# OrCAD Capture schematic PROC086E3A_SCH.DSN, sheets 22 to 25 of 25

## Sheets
22 11. AUDIO I/F - CODEC - B: size C; title: AUDIO I/F CODEC - B
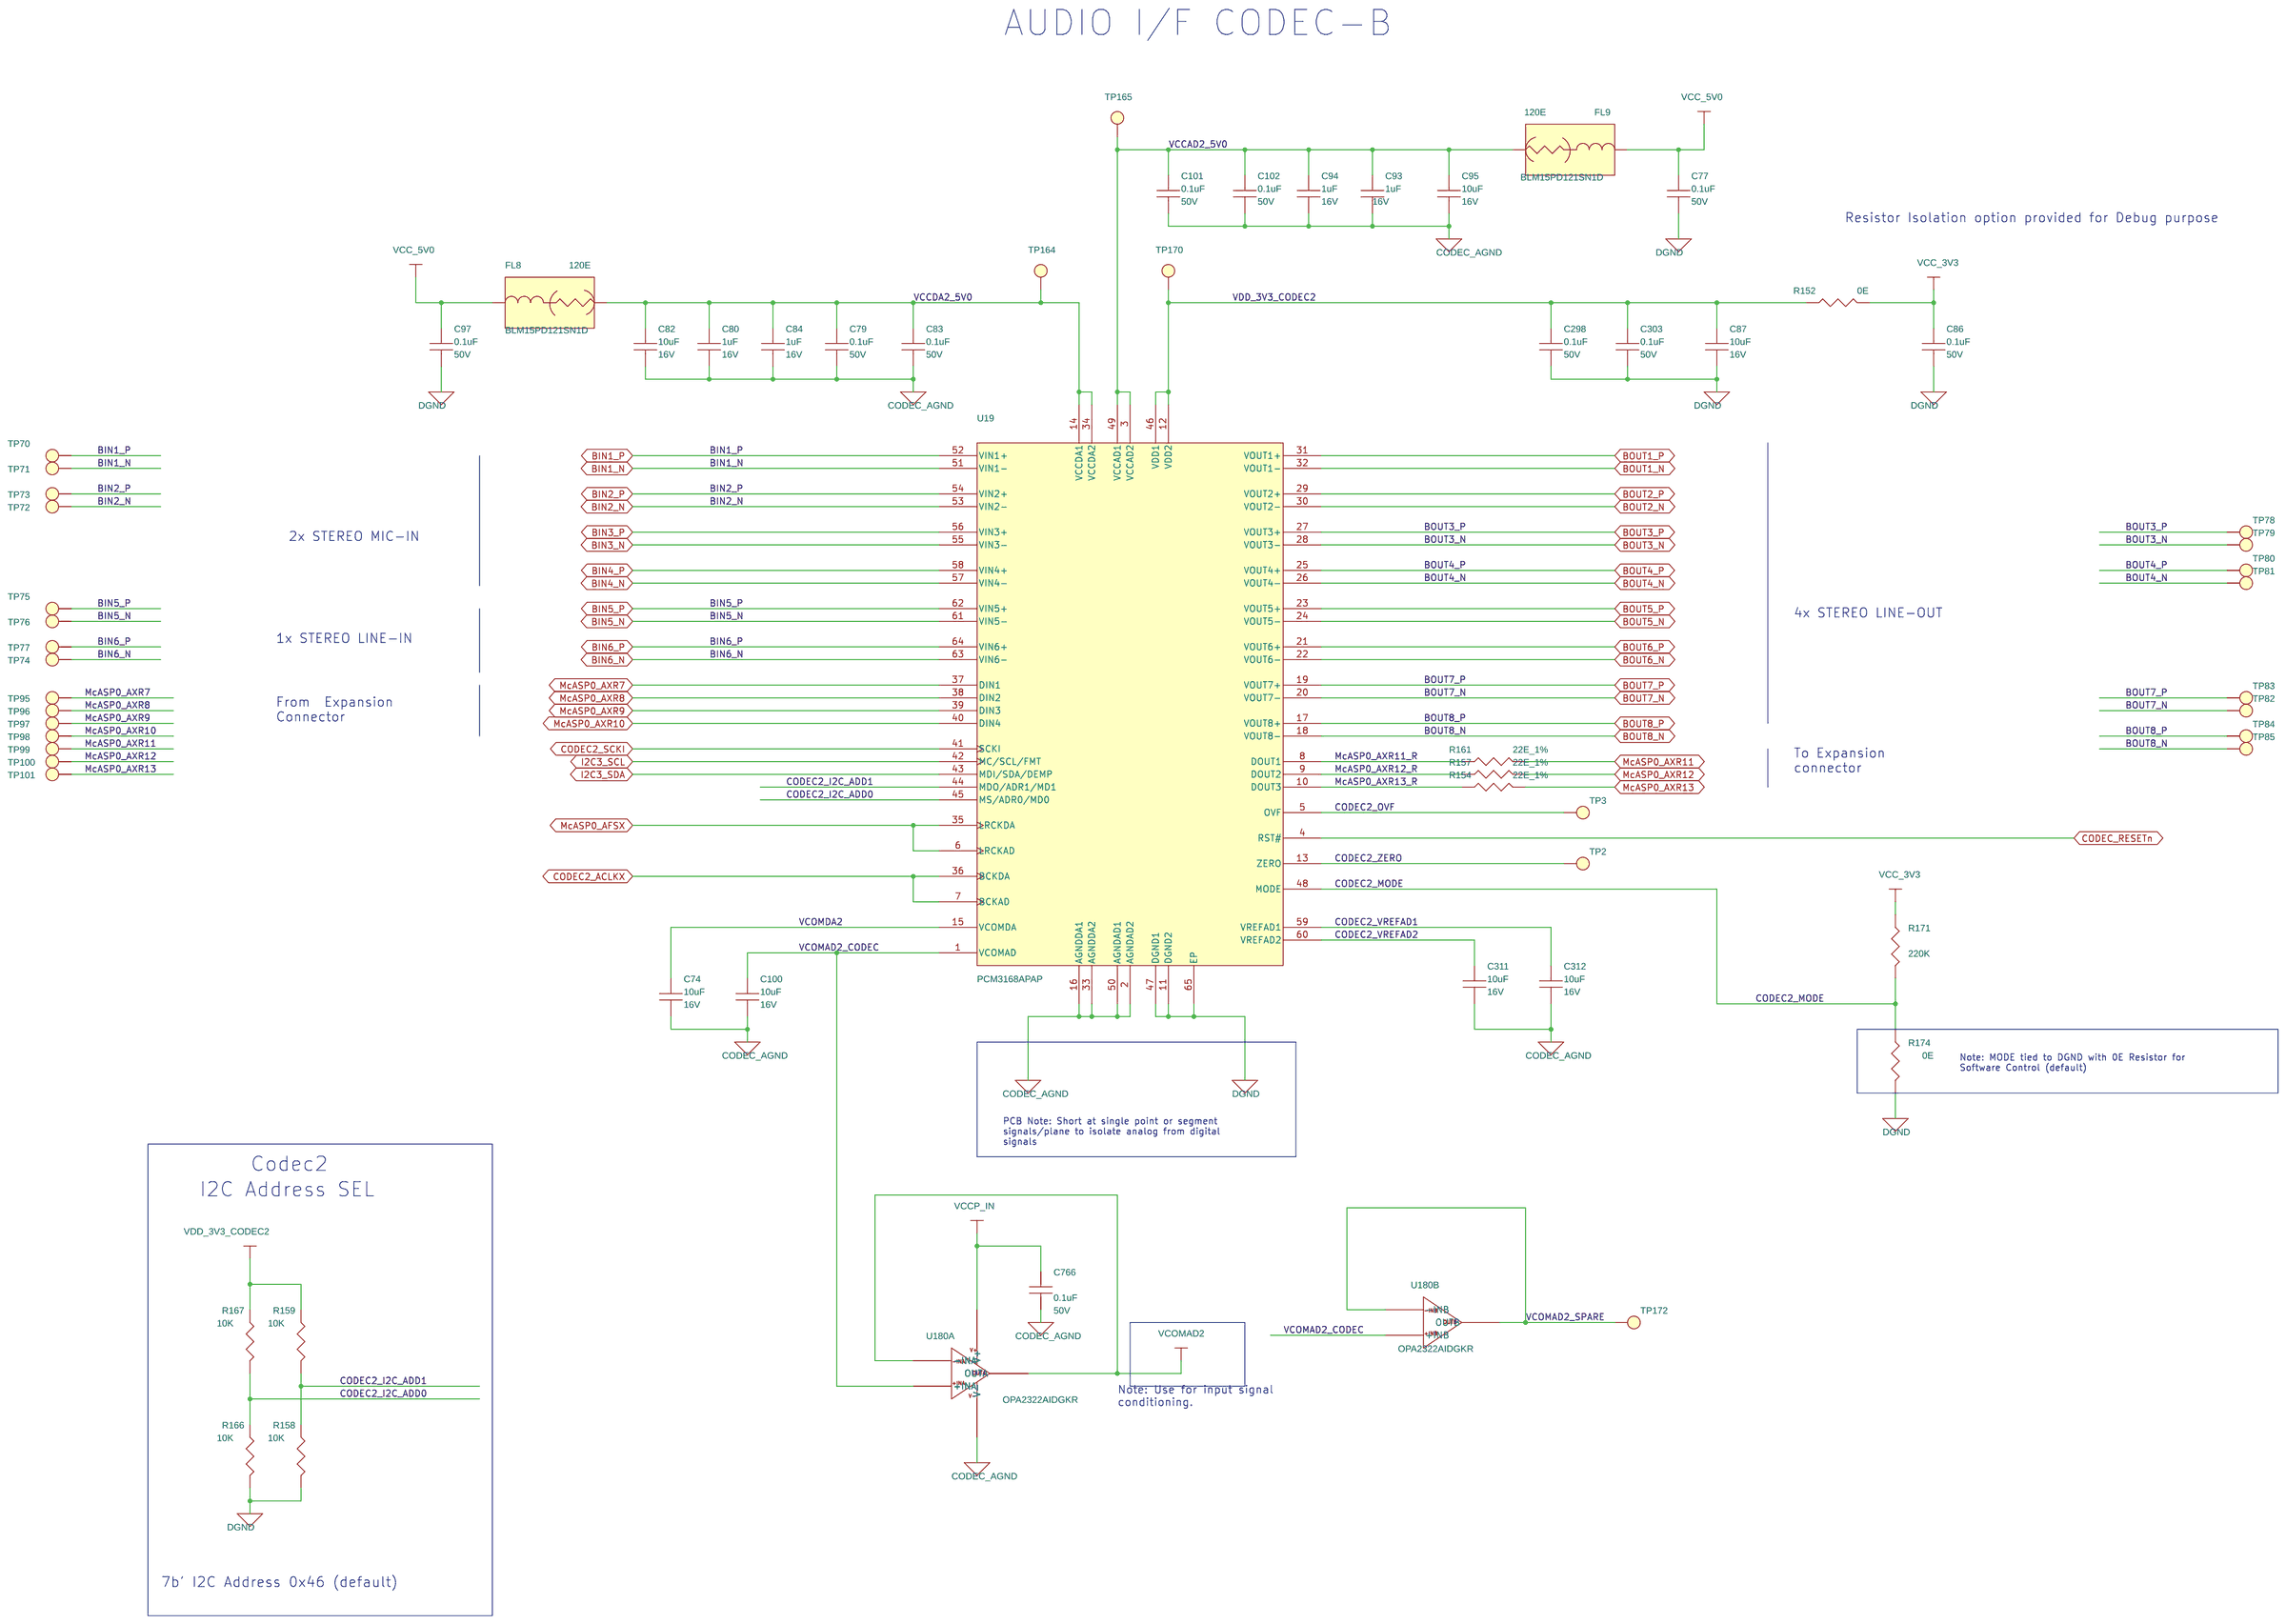
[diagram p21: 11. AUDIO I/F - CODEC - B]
23 06. AUDIO I/F - CODEC - A: size C; title: AUDIO I/F CODEC - A
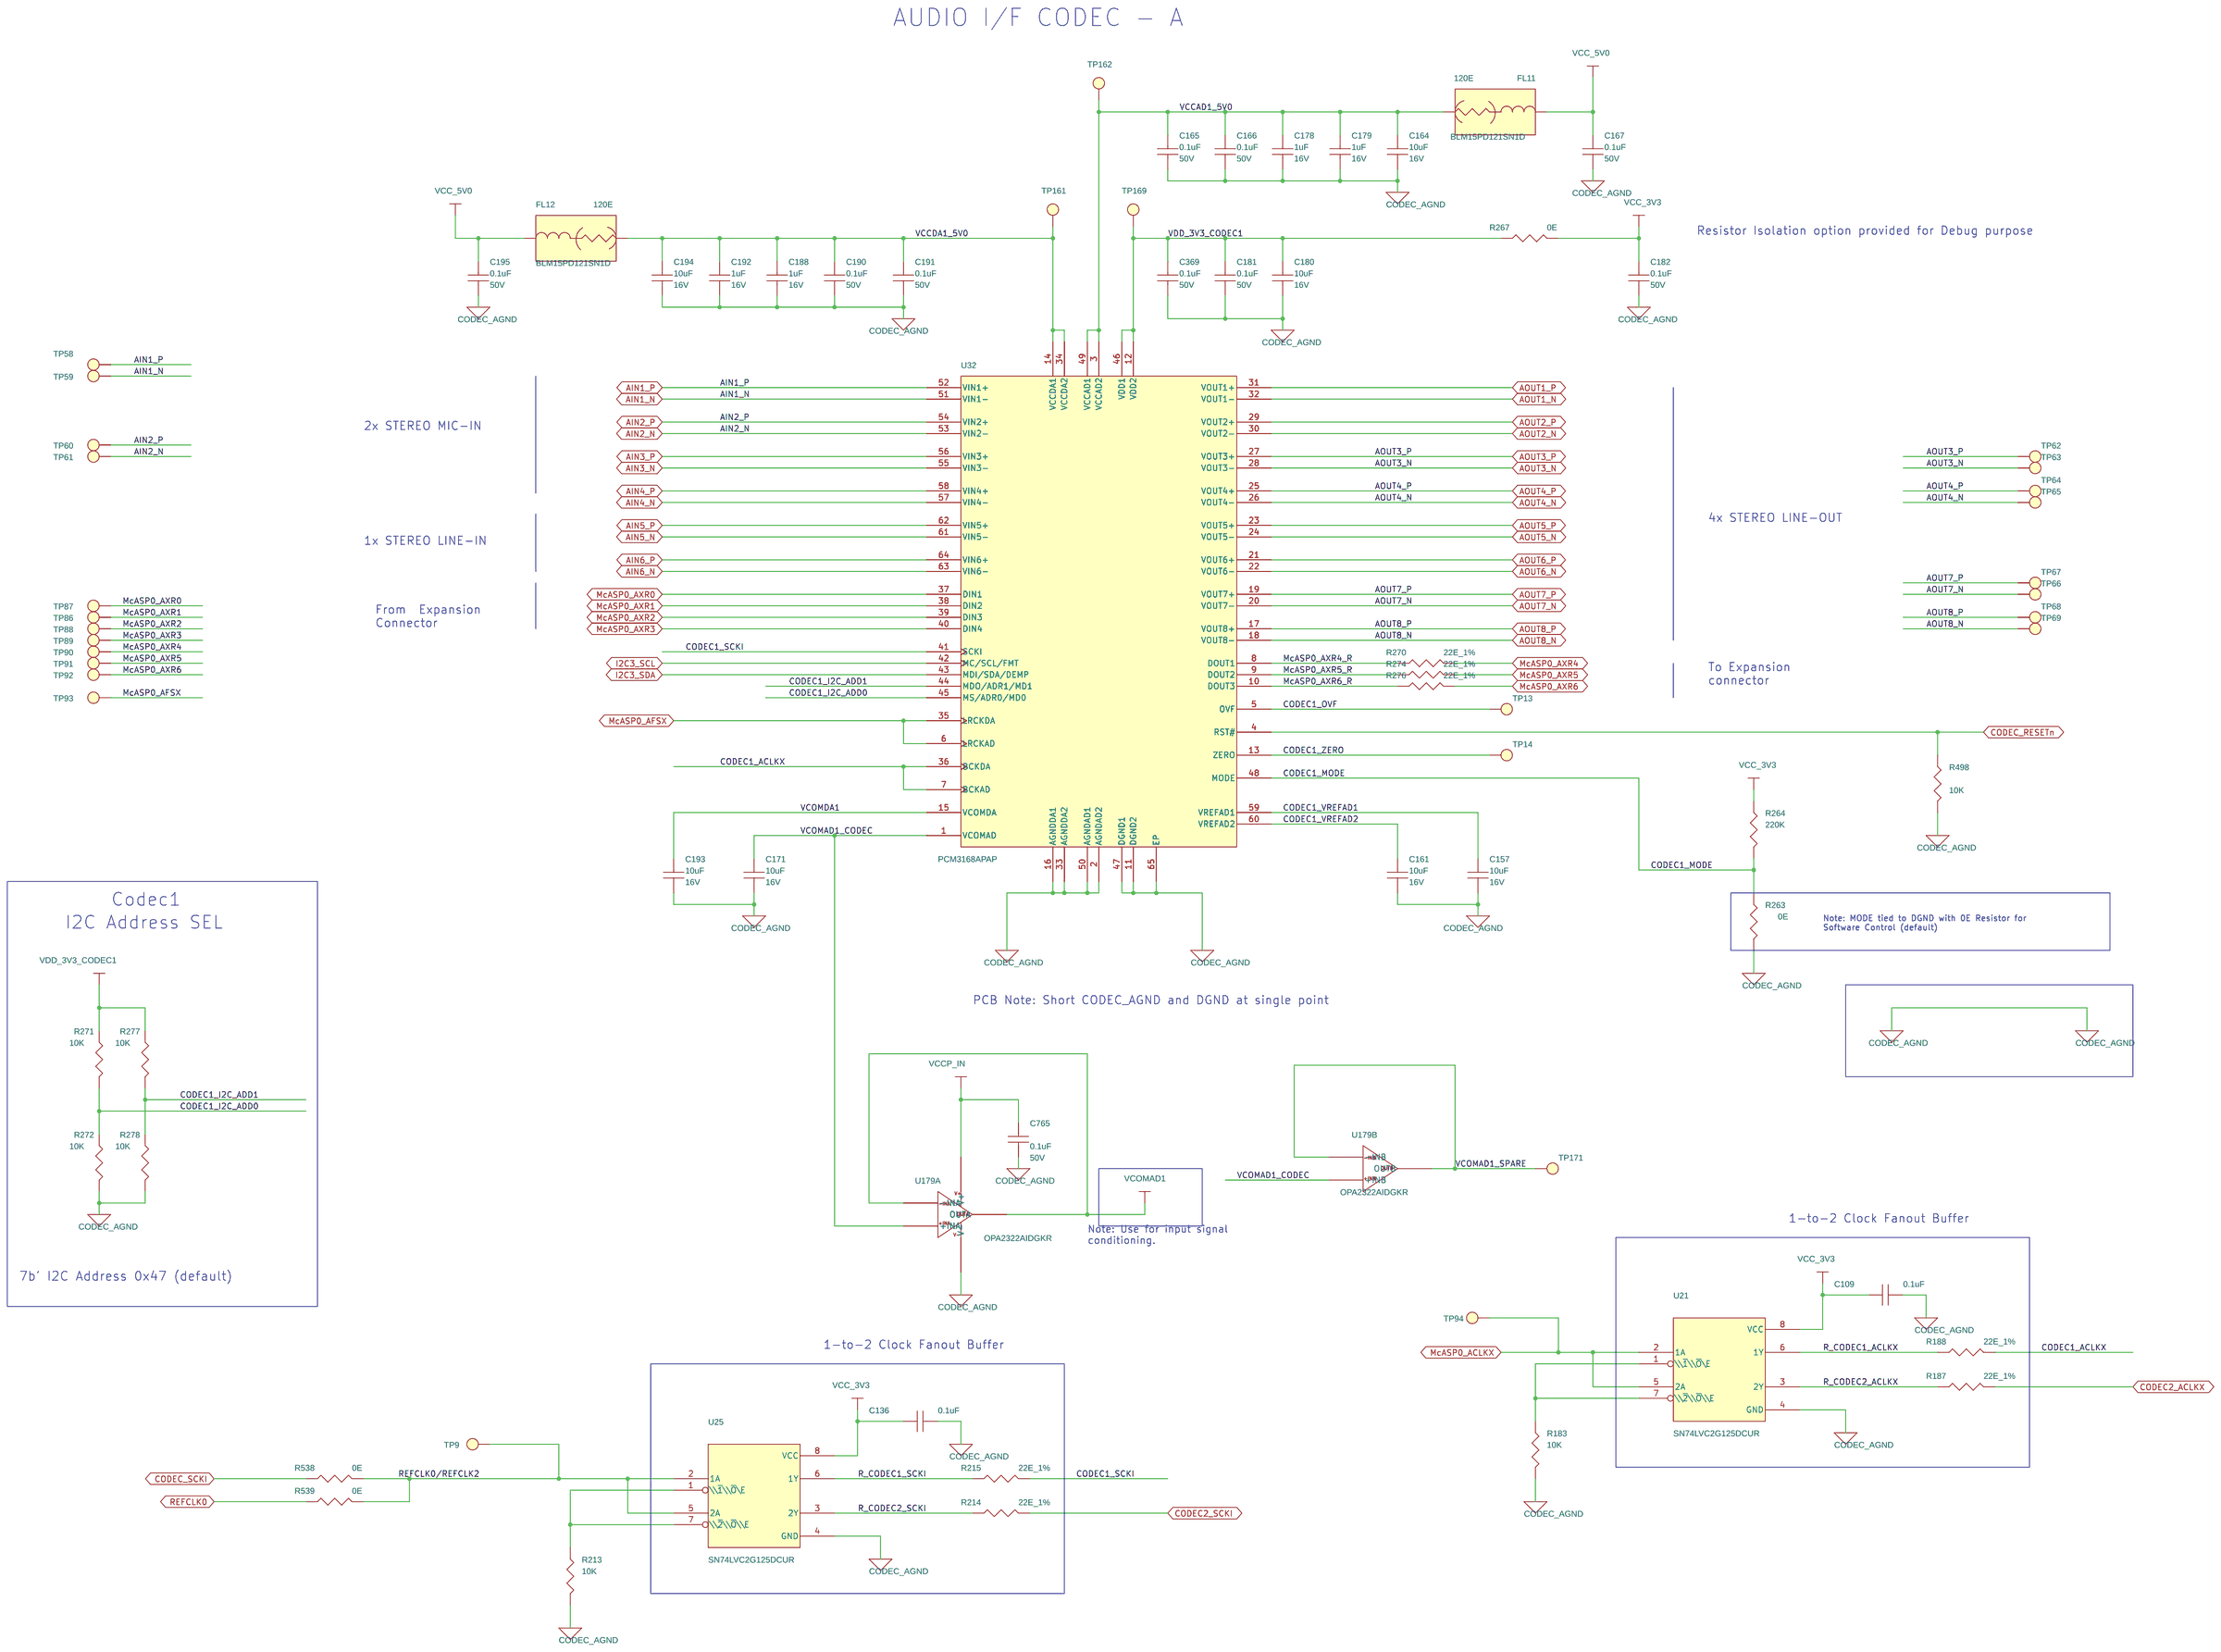
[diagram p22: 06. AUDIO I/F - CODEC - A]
24 04. GPIO EXPANDER MAP/TABLE: title: GPIO EXPANDER MAP/TABLE
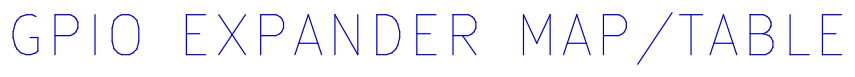
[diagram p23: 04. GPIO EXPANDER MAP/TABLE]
25 23. DIR I/P SELECTION & DIT I/F: size C; title: DIR INPUT SELECTION
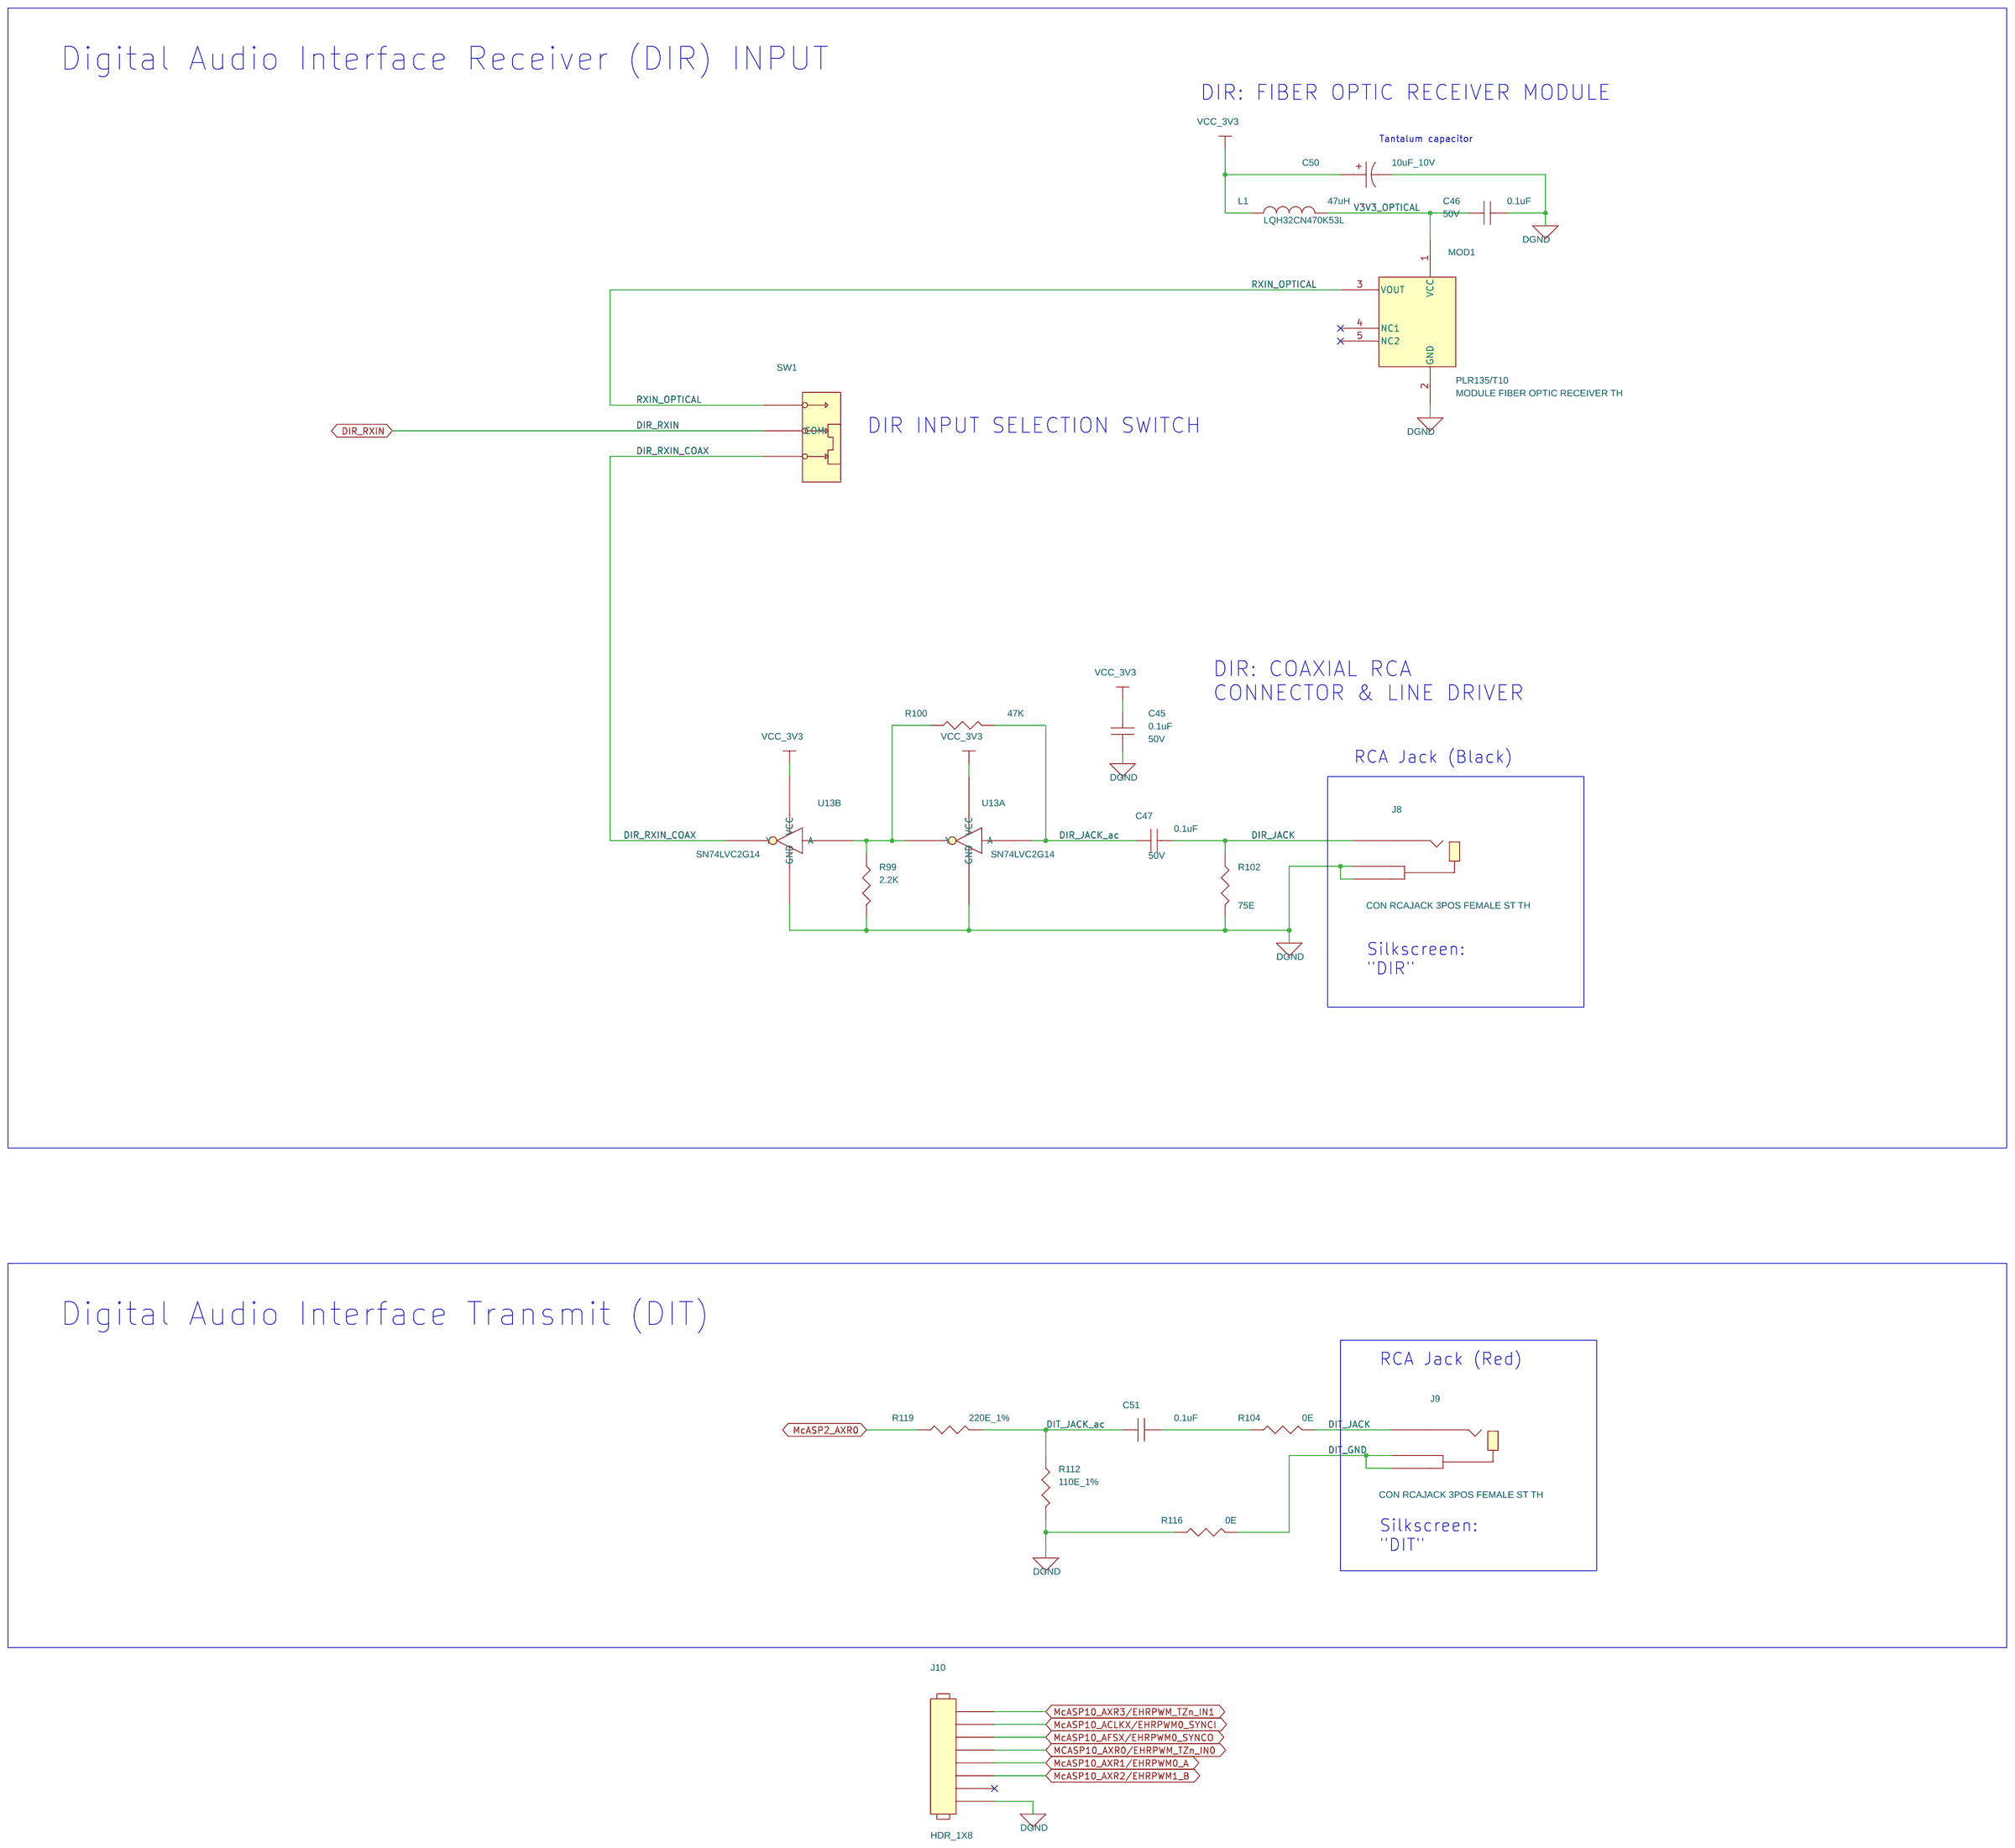
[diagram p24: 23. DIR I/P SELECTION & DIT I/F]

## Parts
sheet 06. AUDIO I/F - CODEC - A
C109  0.1uF  [CAP0402_0-75]
C136  0.1uF  [CAP0402_0-75]
C157  10uF  [CAP0603_1]
C161  10uF  [CAP0603_1]
C164  10uF  [CAP0603_1]
C165  0.1uF  [CAP0402_0-75]
C166  0.1uF  [CAP0402_0-75]
C167  0.1uF  [CAP0402_0-75]
C171  10uF  [CAP0603_1]
C178  1uF  [CAP0402_0-5]
C179  1uF  [CAP0402_0-5]
C180  10uF  [CAP0603_1]
C181  0.1uF  [CAP0402_0-75]
C182  0.1uF  [CAP0402_0-75]
C188  1uF  [CAP0402_0-5]
C190  0.1uF  [CAP0402_0-75]
C191  0.1uF  [CAP0402_0-75]
C192  1uF  [CAP0402_0-5]
C193  10uF  [CAP0603_1]
C194  10uF  [CAP0603_1]
C195  0.1uF  [CAP0402_0-75]
C369  0.1uF  [CAP0402_0-75]
C765  0.1uF  [CAP0402_0-75]
FL11  120E  [EMIFIL_BLM15A_0402_0-6]
FL12  120E  [EMIFIL_BLM15A_0402_0-6]
R183  10K  [RES0402_0-5]
R187  22E_1%  [RES0402_0-5]
R188  22E_1%  [RES0402_0-5]
R213  10K  [RES0402_0-5]
R214  22E_1%  [RES0402_0-5]
R215  22E_1%  [RES0402_0-5]
R263  0E  [RES0402_0-5]
R264  220K  [RES0402_0-5]
R267  0E  [RES0402_0-5]
R270  22E_1%  [RES0402_0-5]
R271  10K  [RES0402_0-5]
R272  10K  [RES0402_0-5]
R274  22E_1%  [RES0402_0-5]
R276  22E_1%  [RES0402_0-5]
R277  10K  [RES0402_0-5]
R278  10K  [RES0402_0-5]
R498  10K  [RES0402_0-5]
R538  0E  [RES0402_0-5]
R539  0E  [RES0402_0-5]
TP9  TP40_SMD  [TP40_SMD]
TP13  TP40_SMD  [TP40_SMD]
TP14  TP40_SMD  [TP40_SMD]
TP58  TP20_SMD  [TP20_SMD]
TP59  TP20_SMD  [TP20_SMD]
TP60  TP20_SMD  [TP20_SMD]
TP61  TP20_SMD  [TP20_SMD]
TP62  TP20_SMD  [TP20_SMD]
TP63  TP20_SMD  [TP20_SMD]
TP64  TP20_SMD  [TP20_SMD]
TP65  TP20_SMD  [TP20_SMD]
TP66  TP20_SMD  [TP20_SMD]
TP67  TP20_SMD  [TP20_SMD]
TP68  TP20_SMD  [TP20_SMD]
TP69  TP20_SMD  [TP20_SMD]
TP86  TP20_SMD  [TP20_SMD]
TP87  TP20_SMD  [TP20_SMD]
TP88  TP20_SMD  [TP20_SMD]
TP89  TP20_SMD  [TP20_SMD]
TP90  TP20_SMD  [TP20_SMD]
TP91  TP20_SMD  [TP20_SMD]
TP92  TP20_SMD  [TP20_SMD]
TP93  TP20_SMD  [TP20_SMD]
TP94  TP20_SMD  [TP20_SMD]
TP161  TP40_SMD  [TP40_SMD]
TP162  TP40_SMD  [TP40_SMD]
TP169  TP40_SMD  [TP40_SMD]
TP171  TP40_SMD  [TP40_SMD]
U21  SN74LVC2G125DCUR  [VSSOP8_19-68_85X95]
U25  SN74LVC2G125DCUR  [VSSOP8_19-68_85X95]
U32  PCM3168APAP  [HTQFP64_19-68_400X400_1-2_EP7-3X7]
U179  OPA2322AIDGKR  [VSSOP8_25-59_120X120_1-1]  (sections A,B)
sheet 11. AUDIO I/F - CODEC - B
C74  10uF  [CAP0603_1]
C77  0.1uF  [CAP0402_0-75]
C79  0.1uF  [CAP0402_0-75]
C80  1uF  [CAP0402_0-5]
C82  10uF  [CAP0603_1]
C83  0.1uF  [CAP0402_0-75]
C84  1uF  [CAP0402_0-5]
C86  0.1uF  [CAP0402_0-75]
C87  10uF  [CAP0603_1]
C93  1uF  [CAP0402_0-5]
C94  1uF  [CAP0402_0-5]
C95  10uF  [CAP0603_1]
C97  0.1uF  [CAP0402_0-75]
C100  10uF  [CAP0603_1]
C101  0.1uF  [CAP0402_0-75]
C102  0.1uF  [CAP0402_0-75]
C298  0.1uF  [CAP0402_0-75]
C303  0.1uF  [CAP0402_0-75]
C311  10uF  [CAP0603_1]
C312  10uF  [CAP0603_1]
C766  0.1uF  [CAP0402_0-75]
FL8  120E  [EMIFIL_BLM15A_0402_0-6]
FL9  120E  [EMIFIL_BLM15A_0402_0-6]
R152  0E  [RES0402_0-5]
R154  22E_1%  [RES0402_0-5]
R157  22E_1%  [RES0402_0-5]
R158  10K  [RES0402_0-5]
R159  10K  [RES0402_0-5]
R161  22E_1%  [RES0402_0-5]
R166  10K  [RES0402_0-5]
R167  10K  [RES0402_0-5]
R171  220K  [RES0402_0-5]
R174  0E  [RES0402_0-5]
TP2  TP40_SMD  [TP40_SMD]
TP3  TP40_SMD  [TP40_SMD]
TP70  TP20_SMD  [TP20_SMD]
TP71  TP20_SMD  [TP20_SMD]
TP72  TP20_SMD  [TP20_SMD]
TP73  TP20_SMD  [TP20_SMD]
TP74  TP20_SMD  [TP20_SMD]
TP75  TP20_SMD  [TP20_SMD]
TP76  TP20_SMD  [TP20_SMD]
TP77  TP20_SMD  [TP20_SMD]
TP78  TP20_SMD  [TP20_SMD]
TP79  TP20_SMD  [TP20_SMD]
TP80  TP20_SMD  [TP20_SMD]
TP81  TP20_SMD  [TP20_SMD]
TP82  TP20_SMD  [TP20_SMD]
TP83  TP20_SMD  [TP20_SMD]
TP84  TP20_SMD  [TP20_SMD]
TP85  TP20_SMD  [TP20_SMD]
TP95  TP20_SMD  [TP20_SMD]
TP96  TP20_SMD  [TP20_SMD]
TP97  TP20_SMD  [TP20_SMD]
TP98  TP20_SMD  [TP20_SMD]
TP99  TP20_SMD  [TP20_SMD]
TP100  TP20_SMD  [TP20_SMD]
TP101  TP20_SMD  [TP20_SMD]
TP164  TP40_SMD  [TP40_SMD]
TP165  TP40_SMD  [TP40_SMD]
TP170  TP40_SMD  [TP40_SMD]
TP172  TP40_SMD  [TP40_SMD]
U19  PCM3168APAP  [HTQFP64_19-68_400X400_1-2_EP7-3X7]
U180  OPA2322AIDGKR  [VSSOP8_25-59_120X120_1-1]  (sections A,B)
sheet 23. DIR I/P SELECTION & DIT I/F
C45  0.1uF  [CAP0402_0-75]
C46  0.1uF  [CAP0402_0-75]
C47  0.1uF  [CAP0402_0-75]
C50  10uF_10V  [CAPCT0805H_1]
C51  0.1uF  [CAP0402_0-75]
J8  CON_RCAJACK3_RCJ-022  [CON_RCAJACK3_RCJ-02X_S_S_T_16]
J9  CON_RCAJACK3_RCJ-022  [CON_RCAJACK3_RCJ-02X_S_S_T_16]
J10  HDR_1X8  [HDR_1X8_77311-818-08_S_T_8-6]
L1  47uH  [INDP1210]
MOD1  PLR135/T10  [MOD5_PLR135T10]
R99  2.2K  [RES0402_0-5]
R100  47K  [RES0402_0-5]
R102  75E  [RES0402_0-5]
R104  0E  [RES0402_0-5]
R112  110E_1%  [RES0402_0-5]
R116  0E  [RES0402_0-5]
R119  220E_1%  [RES0402_0-5]
SW1  EG-1218  [SW3_98-42_460X160_TH]
U13  SN74LVC2G14  [SC70-6]  (sections A,B)

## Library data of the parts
C45-C47 C51 C77 C79 C83 C86 C97 C101 C102 C109 C136 C165-C167 C181 C182 C190 C191 C195 C298 C303 C369 = CAP: CAP CERAMIC 0.1uF 50V 10% X7R 0402; Chkd/date: VASANTHA/281216; Crtd /date: CHAITHANYA/051011; Custom_Duty: 15%; Customs_HS_Code: 85322990; Distributor_name: DIGIKEY; Distributor_part_number: 445-173610-1-ND; Footprint Path: Y:\MIS_DATABASE\Library\ALTIUM_TOOL\PCB_FOOTPRINTS\Altium_Footprint_Lib.PcbLib; Height: 0.60MM; Library Path: Y:\MIS_DATABASE\Library\ALTIUM_TOOL\SCHEMATICS_PARTS\MS_DISCRETE_Library.schlib; Mfr_name: TDK CORPORATION; Mfr_part_number: C1005X7R1H104K050BE; Mistral Part No: 120011100014-R; Package: 0402; Part_type: CAPACITORS\CERAMIC; Project: VP-4000-BASE-BOARD; RoHS: RoHS; Temperature: -55°C+125°C; Tolerance: 10%; Voltage: 50V; Wattage: NA; Weight: 0.65mg; Datasheet: Y:\MIS_DATABASE\DATASHEETS\CAPACITORS\TDK_C-SER_FEB19.PDF
C74 C82 C87 C95 C100 C157 C161 C164 C171 C180 C193 C194 C311 C312 = CAP: CAP CERAMIC 10uF 16V 20% X6S 0603; Chkd/date: VASANTHA/170117; Crtd /date: VASANTHA/170117; Custom_Duty: 15%; Customs_HS_Code: 85322990; Distributor_name: DIGIKEY; Distributor_part_number: 490-7198-1-ND; Footprint Path: Y:\MIS_DATABASE\Library\ALTIUM_TOOL\PCB_FOOTPRINTS\Altium_Footprint_Lib.PcbLib; Height: 0.90MM; Library Path: Y:\MIS_DATABASE\Library\ALTIUM_TOOL\SCHEMATICS_PARTS\MS_DISCRETE_Library.schlib; Mfr_name: MURATA; Mfr_part_number: GRM188C81C106MA73D; Mistral Part No: 120017010004-R; Package: 0603; Part_type: CAPACITORS\CERAMIC; Project: TRMM_SMART-M_PS; RoHS: RoHS; Temperature: -55°C+105°C; Tolerance: 20%; Voltage: 16V; Wattage: NA; Weight: 6.3mg; Datasheet: Y:\MIS_DATABASE\DATASHEETS\CAPACITORS\MURATA-GXX-SER_NOV17.PDF
C80 C84 C93 C94 C178 C179 C188 C192 = CAP: CAP CERAMIC 1uF 16V 10% X5R 0402; Chkd/date: MANIRAJA/260618; Crtd /date: ALVY/260618; Custom_Duty: 15%; Customs_HS_Code: 85322990; Distributor_name: DIGIKEY; Distributor_part_number: 445-13181-1-ND; Footprint Path: Y:\MIS_DATABASE\Library\ALTIUM_TOOL\PCB_FOOTPRINTS\Altium_Footprint_Lib.PcbLib; Height: 0.33MM; Library Path: Y:\MIS_DATABASE\Library\ALTIUM_TOOL\SCHEMATICS_PARTS\MS_DISCRETE_Library.schlib; Mfr_name: TDK CORPORATION; Mfr_part_number: CGB2A1X5R1C105K033BC; Mistral Part No: 120018060036-R; Package: 0402; Part_type: CAPACITORS\CERAMIC; Project: MYTHIC_PCIE_DB; RoHS: RoHS; Temperature: -55°C+85°C; Tolerance: 10%; Voltage: 16V; Wattage: NA; Weight: 0.65mg; Datasheet: Y:\MIS_DATABASE\DATASHEETS\CAPACITORS\TDK-CG-SER.PDF
C765 C766 = CAP: CAP CERAMIC 0.1uF 50V 10% X7R 0402; Chkd/date: MANIRAJA/230418; Crtd /date: ALVY/230418; Custom_Duty: 15%; Customs_HS_Code: 85322990; Distributor_name: DIGIKEY; Distributor_part_number: 587-3498-1-ND; Footprint Path: Y:\MIS_DATABASE\Library\ALTIUM_TOOL\PCB_FOOTPRINTS\Altium_Footprint_Lib.PcbLib; Height: 0.55MM; Library Path: Y:\MIS_DATABASE\Library\ALTIUM_TOOL\SCHEMATICS_PARTS\MS_DISCRETE_Library.schlib; Mfr_name: TAIYO YUDEN; Mfr_part_number: UMK105B7104KV-FR; Mistral Part No: 120011100014-R; Package: 0402; Part_type: CAPACITORS\CERAMIC; Project: GC150_PHASE-II_AB; RoHS: RoHS; Temperature: -55°C+125°C; Tolerance: 10%; Voltage: 50V; Wattage: NA; Weight: 0.65mg; Datasheet: Y:\MIS_DATABASE\DATASHEETS\CAPACITORS\UMK105B7104KV-FR.PDF
FL8 FL9 FL11 FL12 = EMIFILTER_IND: IND FERRITE BEAD CHIP 120E 1.3A 0402; Chkd/date: VASANTHA/010117; Crtd /date: CHAITHANYA/150312; Custom_Duty: 24%; Customs_HS_Code: 85437099; Distributor_name: DIGIKEY; Distributor_part_number: 490-5203-1-ND; Footprint Path: Y:\MIS_DATABASE\Library\ALTIUM_TOOL\PCB_FOOTPRINTS\Altium_Footprint_Lib.PcbLib; Height: 0.55MM; Library Path: Y:\MIS_DATABASE\Library\ALTIUM_TOOL\SCHEMATICS_PARTS\MS_FILTER_Library.schlib; Mfr_name: MURATA; Mfr_part_number: BLM15PD121SN1D; Mistral Part No: 130012030043-R; Package: 0402; Part_type: FILTER; Project: GEN_3-8; RoHS: RoHS; Temperature: -55°C+125°C; Tolerance: 25%; Voltage: NA; Wattage: NA; Weight: 0.65mg; Datasheet: Y:\MIS_DATABASE\DATASHEETS\DISCRETES\INDUCTORS\BLM15X-SER.PDF
R159 R166 R183 R213 R271 R277 R498 = RESISTOR: RES 10K 1/16W 5% 0402; Chkd/date: VASANTHA/061216; Crtd /date: MAZHAR/230805; Custom_Duty: 15%; Customs_HS_Code: 85332119; Distributor_name: DIGIKEY; Distributor_part_number: 311-10KJRCT-ND; Footprint Path: Y:\MIS_DATABASE\Library\ALTIUM_TOOL\PCB_FOOTPRINTS\Altium_Footprint_Lib.PcbLib; Height: 0.40MM; Library Path: Y:\MIS_DATABASE\Library\ALTIUM_TOOL\SCHEMATICS_PARTS\MS_DISCRETE_Library.schlib; Mfr_name: YAGEO AMERICA; Mfr_part_number: RC0402JR-0710KL; Mistral Part No: 110011060021-R; Package: 0402; Part_type: RESISTORS\FIXED; Project: HSE; RoHS: RoHS; Temperature: -55°C+155°C; Tolerance: 5%; Voltage: NA; Wattage: 1/16W; Weight: 0.65mg; Datasheet: Y:\MIS_DATABASE\DATASHEETS\RESISTORS\RCXXXXL-SER_MAR18.PDF
R154 R157 R161 R187 R188 R214 R215 R270 R274 R276 = RESISTOR: RES 22E 1/16W 1% 0402; Chkd/date: SUHAS/290910; Crtd /date: MAZHAR/090909; Cust_part_number: 4700-80047E; Custom_Duty: 15%; Customs_HS_Code: 85332119; Distributor_name: DIGIKEY; Distributor_part_number: 311-22.0LRCT-ND; Footprint Path: Y:\MIS_DATABASE\Library\ALTIUM_TOOL\PCB_FOOTPRINTS\Altium_Footprint_Lib.PcbLib; Height: 0.40MM; Library Path: Y:\MIS_DATABASE\Library\ALTIUM_TOOL\SCHEMATICS_PARTS\MS_DISCRETE_Library.schlib; Mfr_name: YAGEO AMERICA; Mfr_part_number: RC0402FR-0722RL; Mistral Part No: 110009090004-R; Package: 0402; Part_type: RESISTORS\FIXED; Project: VMEFMCD; RoHS: RoHS; Temperature: -55°C+155°C; Tolerance: 1%; Voltage: NA; Wattage: 1/16W; Weight: 0.65mg; Datasheet: Y:\MIS_DATABASE\DATASHEETS\RESISTORS\RCXXXXL-SER_MAR18.PDF
R104 R116 R152 R174 R263 R267 R538 R539 = RESISTOR: RES 0E 1/10W JUMPER 0402; Chkd/date: VASANTHA/061216; Crtd /date: NAVEED/201014; Custom_Duty: 15%; Customs_HS_Code: 85332119; Distributor_name: DIGIKEY; Distributor_part_number: P0.0JCT-ND; Footprint Path: Y:\MIS_DATABASE\Library\ALTIUM_TOOL\PCB_FOOTPRINTS\Altium_Footprint_Lib.PcbLib; Height: 0.40MM; IBISSP_MODLES: VALUE REPEATING 2 TIME; Library Path: Y:\MIS_DATABASE\Library\ALTIUM_TOOL\SCHEMATICS_PARTS\MS_DISCRETE_Library.schlib; Mfr_name: PANASONIC-ECG; Mfr_part_number: ERJ-2GE0R00X; Mistral Part No: 110018030052-R; Package: 0402; Part_type: RESISTORS\FIXED; Project: AEGIS POM; RoHS: RoHS; Temperature: -55°C+155°C; Tolerance: NA; Voltage: NA; Wattage: 1/10W; Weight: 0.8mg; Datasheet: Y:\MIS_DATABASE\DATASHEETS\RESISTORS\PAN-ERJSER_NOV17.PDF
R171 R264 = RESISTOR: RES 220K 1/16W 5% 0402; Assembly_Instruction: DNI; Chkd/date: SHREESHAIL/061205; Crtd /date: MAZHAR/130705; Custom_Duty: 15%; Customs_HS_Code: 85332119; Distributor_name: DIGIKEY; Distributor_part_number: 311-220KJRDKR-ND; Footprint Path: Y:\MIS_DATABASE\Library\ALTIUM_TOOL\PCB_FOOTPRINTS\Altium_Footprint_Lib.PcbLib; Height: 0.40MM; Library Path: Y:\MIS_DATABASE\Library\ALTIUM_TOOL\SCHEMATICS_PARTS\MS_DISCRETE_Library.schlib; Mfr_name: YAGEO AMERICA; Mfr_part_number: RC0402JR-07220KL; Mistral Part No: 110009030510-R; Package: 0402; Part_type: RESISTORS\FIXED; Project: PMP-VIOMEDIA; RoHS: RoHS; Temperature: -55°C+155°C; Tolerance: 5%; Voltage: NA; Wattage: 1/16W; Weight: 0.65mg; Datasheet: Y:\MIS_DATABASE\DATASHEETS\RESISTORS\RCXXXXL-SER_MAR18.PDF
R158 R167 R272 R278 = RESISTOR: RES 10K 1/16W 5% 0402; Assembly_Instruction: DNI; Chkd/date: VASANTHA/061216; Crtd /date: MAZHAR/230805; Custom_Duty: 15%; Customs_HS_Code: 85332119; Distributor_name: DIGIKEY; Distributor_part_number: 311-10KJRCT-ND; Footprint Path: Y:\MIS_DATABASE\Library\ALTIUM_TOOL\PCB_FOOTPRINTS\Altium_Footprint_Lib.PcbLib; Height: 0.40MM; Library Path: Y:\MIS_DATABASE\Library\ALTIUM_TOOL\SCHEMATICS_PARTS\MS_DISCRETE_Library.schlib; Mfr_name: YAGEO AMERICA; Mfr_part_number: RC0402JR-0710KL; Mistral Part No: 110011060021-R; Package: 0402; Part_type: RESISTORS\FIXED; Project: HSE; RoHS: RoHS; Temperature: -55°C+155°C; Tolerance: 5%; Voltage: NA; Wattage: 1/16W; Weight: 0.65mg; Datasheet: Y:\MIS_DATABASE\DATASHEETS\RESISTORS\RCXXXXL-SER_MAR18.PDF
TP2 TP3 TP9 TP13 TP14 TP161 TP162 TP164 TP165 TP169-TP172 = TESTPOINT: TESTPOINT CIR 40 SMD; Chkd/date: MAZHAR/190505; Crtd /date: MAZHAR/190505; Distributor_name: NA; Distributor_part_number: NA; Footprint Path: Y:\MIS_DATABASE\Library\ALTIUM_TOOL\PCB_FOOTPRINTS\Altium_Footprint_Lib.PcbLib; Height: NA; Library Path: Y:\MIS_DATABASE\Library\ALTIUM_TOOL\SCHEMATICS_PARTS\MS_DISCRETE_Library.schlib; MECHANICAL 3D STEP FILE: NA; Mfr_name: LOCAL; Mistral Part No: 130009030933; Package: SMD; Project: RAINIER-3; RoHS: NA; Temperature: NA; Tolerance: NA; Voltage: NA; Wattage: NA; Weight: NA; Datasheet: NA
TP58-TP101 = TESTPOINT: TESTPOINT CIR 20 SMD; Chkd/date: SHREESHAIL/171006; Crtd /date: MAZHAR/171006; Custom_Duty: NA; Customs_HS_Code: NA; Distributor_name: NA; Distributor_part_number: NA; Footprint Path: Y:\MIS_DATABASE\Library\ALTIUM_TOOL\PCB_FOOTPRINTS\Altium_Footprint_Lib.PcbLib; Height: NA; Library Path: Y:\MIS_DATABASE\Library\ALTIUM_TOOL\SCHEMATICS_PARTS\MS_DISCRETE_Library.schlib; MECHANICAL 3D STEP FILE: NA; Mfr_name: LOCAL; Mistral Part No: NA; Package: SMD; Project: BT MODULE_CSRBC04; RoHS: NA; Temperature: NA; Tolerance: NA; Voltage: NA; Wattage: NA; Weight: NA; Datasheet: NA
U21 U25 = SN74LVC2G125DCUT_VSSOP8: IC DUAL BUS BUFFER GATE VSSOP8; Chkd/date: SHREESHAIL/060607; Crtd /date: MAZHAR/170107; Custom_Duty: 15%; Customs_HS_Code: 85423100; Distributor_name: DIGIKEY; Distributor_part_number: 296-13265-1-ND; Height: 0.90MM; Mfr_name: TEXAS INSTRUMENTS; Mistral Part No: 141009030242-R; Package: VSSOP8; Part_type: ICS\DIGITAL\GATES; Project: OMAP2430_OSK; RoHS: RoHS; Temperature: -40°C+85°C; Tolerance: NA; Voltage: NA; Wattage: NA; Weight: NA; Datasheet: Y:\MIS_DATABASE\DATASHEETS\ICS\DIGITAL\GATES\SN74LVC2G125.PDF
U19 U32 = PCM3168APAP_HTQFP64_TI: IC 24BIT 96KHz/192KHz 6-IN/8-OUT AUDIO CODEC WITH DIFFERENTIAL IN/OUT HTQFP64; Chkd/date: MANIRAJA/140618; Crtd /date: ALVY/140618; Custom_Duty: 15%; Customs_HS_Code: 85423100; Distributor_name: DIGIKEY; Distributor_part_number: 296-23899-5-ND; Footprint Path: Y:\MIS_DATABASE\Library\ALTIUM_TOOL\PCB_FOOTPRINTS\Altium_Footprint_Lib.PcbLib; Height: 1.20MM; Library Path: Y:\MIS_DATABASE\Library\ALTIUM_TOOL\SCHEMATICS_PARTS\MS_TELECOM_Library.schlib; Library Ref: PCM3168APAP_HTQFP64; Mfr_name: TEXAS INSTRUMENTS; Mistral Part No: 143018060003-R; Package: HTQFP64; Part_type: ICS\TELECOM\CODEC; Project: TI_J7SVB_FMZ-BOARD; RoHS: RoHS; Temperature: -40°C+85°C; Tolerance: NA; Voltage: NA; Wattage: NA; Weight: 258.2mg; Datasheet: Y:\MIS_DATABASE\DATASHEETS\ICS\DIGITAL\CODEC\PCM3168A.PDF
U179 U180 = OPA2350UA_SOIC8: IC 20MHz 1.8V LOW NOISE RRI/O CMOS OPAMP VSSOP8; Chkd/date: MANIRAJA/161018; Crtd /date: ALVY/161018; Custom_Duty: 15%; Customs_HS_Code: 85423100; Distributor_name: DIGIKEY; Distributor_part_number: 296-41349-1-ND; Footprint Path: Y:\MIS_DATABASE\Library\ALTIUM_TOOL\PCB_FOOTPRINTS\Altium_Footprint_Lib.PcbLib; Height: 1.10MM; Library Path: Y:\MIS_DATABASE\Library\ALTIUM_TOOL\SCHEMATICS_PARTS\MS_OPAMP_Library.schlib; Mfr_name: TEXAS INSTRUMENTS; Mistral Part No: 140118100019-R; Package: VSSOP8; Part_type: ICS\ANALOG\OPAMP; Project: TI_J7ES_EVM_CP; RoHS: RoHS; Temperature: -40°C+125°C; Tolerance: NA; Voltage: NA; Wattage: NA; Weight: 26.5mg; Datasheet: Y:\MIS_DATABASE\DATASHEETS\ICS\OPAMP\OPA2322XX.PDF
C50 = CAP_POL: CAP TANTALUM 10uF 10V 20% ESR 5E H0805; Chkd/date: MANIRAJA/091018; Crtd /date: ALVY/091018; Custom_Duty: 15%; Customs_HS_Code: 85322990; Distributor_name: DIGIKEY; Distributor_part_number: 478-11046-1-ND; Footprint Path: Y:\MIS_DATABASE\Library\ALTIUM_TOOL\PCB_FOOTPRINTS\Altium_Footprint_Lib.PcbLib; Height: 1.00MM; Library Path: Y:\MIS_DATABASE\Library\ALTIUM_TOOL\SCHEMATICS_PARTS\MS_DISCRETE_Library.schlib; Mfr_name: AVX CORPORATION; Mfr_part_number: TACH106M010XTA; Mistral Part No: 120018100018-R; Package: H0805; Part_type: CAPACITORS\TANTALUM; Project: TI_J7ES_EVM_CP; RoHS: RoHS; Temperature: -55°C+125°C; Tolerance: 20%; Voltage: 10V; Wattage: NA; Weight: 5.5mg; Datasheet: Y:\MIS_DATABASE\DATASHEETS\CAPACITORS\AVX-TAC-APR18.PDF
J8 = CON_RCAJACK3_RCJ-02X: CON RCAJACK 3POS FEMALE ST TH; Chkd/date: MANIRAJA/091118; Crtd /date: MANIRAJA/091118; Custom_Duty: 24%; Customs_HS_Code: 85369090; Distributor_name: DIGIKEY; Distributor_part_number: CP-1406-ND; Footprint Path: Y:\MIS_DATABASE\Library\ALTIUM_TOOL\PCB_FOOTPRINTS\Altium_Footprint_Lib.PcbLib; Height: 15.95MM; Library Path: Y:\MIS_DATABASE\Library\ALTIUM_TOOL\SCHEMATICS_PARTS\MS_CONNECTOR_Library.schlib; Mfr_name: CUI; Mfr_part_number: RCJ-021; Mistral Part No: 150018110010-R; Package: THRU-HOLE; Part_type: CONNECTOR\JACK; Project: TI_J7ES_EVM_IB; RoHS: RoHS; Temperature: -20°C+85°C; Tolerance: NA; Voltage: NA; Wattage: NA; Weight: 2000mg; Datasheet: Y:\MIS_DATABASE\DATASHEETS\CONNECTORS\RCJ-02X.PDF
J9 = CON_RCAJACK3_RCJ-02X: CON RCAJACK 3POS FEMALE ST TH; Chkd/date: MANIRAJA/091118; Crtd /date: MANIRAJA/091118; Custom_Duty: 24%; Customs_HS_Code: 85369090; Distributor_name: DIGIKEY; Distributor_part_number: CP-1407-ND; Footprint Path: Y:\MIS_DATABASE\Library\ALTIUM_TOOL\PCB_FOOTPRINTS\Altium_Footprint_Lib.PcbLib; Height: 15.95MM; Library Path: Y:\MIS_DATABASE\Library\ALTIUM_TOOL\SCHEMATICS_PARTS\MS_CONNECTOR_Library.schlib; Mfr_name: CUI; Mfr_part_number: RCJ-022; Mistral Part No: 150018110009-R; Package: THRU-HOLE; Part_type: CONNECTOR\JACK; Project: TI_J7ES_EVM_IB; RoHS: RoHS; Temperature: -20°C+85°C; Tolerance: NA; Voltage: NA; Wattage: NA; Weight: 2000mg; Datasheet: Y:\MIS_DATABASE\DATASHEETS\CONNECTORS\RCJ-02X.PDF
J10 = HEADER_8X1: CON HDR 1X8 2.54MM PITCH ST TH; Assembly_Instruction: DNI; Chkd/date: MANIRAJA/250718; Crtd /date: ALVY/250718; Custom_Duty: 24%; Customs_HS_Code: 85369090; Distributor_name: DIGIKEY; Distributor_part_number: 609-5130-ND; Footprint Path: Y:\MIS_DATABASE\Library\ALTIUM_TOOL\PCB_FOOTPRINTS\Altium_Footprint_Lib.PcbLib; Height: 8.58MM; Library Path: Y:\MIS_DATABASE\Library\ALTIUM_TOOL\SCHEMATICS_PARTS\MS_CONNECTOR_Library.schlib; Mfr_name: AMPHENOL; Mfr_part_number: 77311-818-08LF; Mistral Part No: 150018070037-R; Package: THRU-HOLE; Part_type: CONNECTOR\HEADERS; Project: PDDS2-CONTROLLER CARD; RoHS: RoHS; Temperature: -65°C+125°C; Tolerance: NA; Voltage: NA; Wattage: NA; Weight: NA; Datasheet: Y:\MIS_DATABASE\DATASHEETS\CONNECTORS\77311-XX.PDF
L1 = INDUCTOR: IND 47uH 170mA 10% 1210; Chkd/date: NAVEED/180814; Crtd /date: VASANTHA/230614; Custom_Duty: 24%; Customs_HS_Code: 85437099; Distributor_name: DIGIKEY; Distributor_part_number: 490-4063-1-ND; Height: 1.70MM; Mfr_name: MURATA; Mfr_part_number: LQH32CN470K53L; Mistral Part No: 130014060042-R; Package: 1210; Project: ASIO; RoHS: RoHS; Temperature: -55°C+125°C; Tolerance: 10%; Voltage: NA; Wattage: NA; Weight: NA; Datasheet: Y:\MIS_DATABASE\DATASHEETS\DISCRETES\INDUCTORS\MURATA-LQH.PDF
MOD1 = MODULE_PLR135T10: MODULE FIBER OPTIC RECEIVER TH; Chkd/date: NAVEED/280115; Crtd /date: JEBRAN/220115; Custom_Duty: 24%; Customs_HS_Code: 85369090; Distributor_name: DIGIKEY; Distributor_part_number: 1080-1433-ND; Height: 10.30MM; Mfr_name: EVERLIGHT ELECTRONICS; Mistral Part No: 180015010002-R; Package: THRU-HOLE; Part_type: MODULE; Project: GALILEO_DAUGHTER_CARD; RoHS: RoHS; Temperature: 20°C+70°C; Tolerance: NA; Voltage: NA; Wattage: NA; Weight: NA; Datasheet: Y:\MIS_DATABASE\DATASHEETS\CONNECTORS\PLR135-10.PDF
R99 = RESISTOR: RES 2.2K 1/10W 5% 0402; Chkd/date: SHREESHAIL/210406; Crtd /date: GEETHA/200406; Custom_Duty: 15%; Customs_HS_Code: 85332119; Distributor_name: DIGIKEY; Distributor_part_number: P2.2KJCT-ND; Footprint Path: Y:\MIS_DATABASE\Library\ALTIUM_TOOL\PCB_FOOTPRINTS\Altium_Footprint_Lib.PcbLib; Height: 0.40MM; Library Path: Y:\MIS_DATABASE\Library\ALTIUM_TOOL\SCHEMATICS_PARTS\MS_DISCRETE_Library.schlib; Mfr_name: PANASONIC-ECG; Mfr_part_number: ERJ-2GEJ222X; Mistral Part No: 110009030429-R; Package: 0402; Part_type: RESISTORS\FIXED; Project: RED EYE; RoHS: RoHS; Temperature: -55°C+155°C; Tolerance: 5%; Voltage: NA; Wattage: 1/10W; Weight: 0.8mg; Datasheet: Y:\MIS_DATABASE\DATASHEETS\RESISTORS\PAN-ERJSER_NOV17.PDF
R100 = RESISTOR: RES 47K 1/10W 5% 0402; Chkd/date: VASANTHA/281216; Crtd /date: MAZHAR/120505; Custom_Duty: 15%; Customs_HS_Code: 85332119; Distributor_name: DIGIKEY; Distributor_part_number: P47KJCT-ND; Footprint Path: Y:\MIS_DATABASE\Library\ALTIUM_TOOL\PCB_FOOTPRINTS\Altium_Footprint_Lib.PcbLib; Height: 0.40MM; Library Path: Y:\MIS_DATABASE\Library\ALTIUM_TOOL\SCHEMATICS_PARTS\MS_DISCRETE_Library.schlib; Mfr_name: PANASONIC-ECG; Mfr_part_number: ERJ-2GEJ473X; Mistral Part No: 110009030882-R; Package: 0402; Part_type: RESISTORS\FIXED; Project: CTP02_REVA_BASE; RoHS: RoHS; Temperature: -55°C+155°C; Tolerance: 5%; Voltage: NA; Wattage: 1/10W; Weight: 0.8mg; Datasheet: Y:\MIS_DATABASE\DATASHEETS\RESISTORS\PAN-ERJSER_NOV17.PDF
R102 = RESISTOR: RES 75E 1/16W 5% AUTO 0402; Chkd/date: SHREESHAIL/170707; Crtd /date: MAZHAR/130707; Custom_Duty: 15%; Customs_HS_Code: 85332119; Distributor_name: DIGIKEY; Distributor_part_number: RHM75JCT-ND; Footprint Path: Y:\MIS_DATABASE\Library\ALTIUM_TOOL\PCB_FOOTPRINTS\Altium_Footprint_Lib.PcbLib; Height: 0.40MM; Library Path: Y:\MIS_DATABASE\Library\ALTIUM_TOOL\SCHEMATICS_PARTS\MS_DISCRETE_Library.schlib; Mfr_name: ROHM; Mfr_part_number: MCR01MZPJ750; Mistral Part No: 110009031102-R; Package: 0402; Part_type: RESISTORS\FIXED; Project: SCRIPTALKMAX; RoHS: RoHS; Temperature: -55°C+155°C; Tolerance: 5%; Voltage: NA; Wattage: 1/16W; Weight: 0.57mg; Datasheet: Y:\MIS_DATABASE\DATASHEETS\RESISTORS\MCR10.PDF
R112 = RESISTOR: RES 110E 1/10W 1% 0402; Chkd/date: MAZHAR/250809; Crtd /date: USMAN/200709; Custom_Duty: 15%; Customs_HS_Code: 85332119; Distributor_name: DIGIKEY; Distributor_part_number: P110LCT-ND; Footprint Path: Y:\MIS_DATABASE\Library\ALTIUM_TOOL\PCB_FOOTPRINTS\Altium_Footprint_Lib.PcbLib; Height: 0.40MM; Library Path: Y:\MIS_DATABASE\Library\ALTIUM_TOOL\SCHEMATICS_PARTS\MS_DISCRETE_Library.schlib; Mfr_name: PANASONIC-ECG; Mfr_part_number: ERJ-2RKF1100X; Mistral Part No: 110009070007-R; Package: 0402; Part_type: RESISTORS\FIXED; Project: PICO PROJECTOR; RoHS: RoHS; Temperature: -55°C+155°C; Tolerance: 1%; Voltage: NA; Wattage: 1/10W; Weight: 0.8mg; Datasheet: Y:\MIS_DATABASE\DATASHEETS\RESISTORS\PAN-ERJSER_NOV17.PDF
R119 = RESISTOR: RES 220E 1/10W 1% 0402; Chkd/date: MANIRAJA/130617; Crtd /date: BAVISH/260711; Custom_Duty: 15%; Customs_HS_Code: 85332119; Distributor_name: DIGIKEY; Distributor_part_number: P220LCT-ND; Footprint Path: Y:\MIS_DATABASE\Library\ALTIUM_TOOL\PCB_FOOTPRINTS\Altium_Footprint_Lib.PcbLib; Height: 0.40MM; Library Path: Y:\MIS_DATABASE\Library\ALTIUM_TOOL\SCHEMATICS_PARTS\MS_DISCRETE_Library.schlib; Mfr_name: PANASONIC-ECG; Mfr_part_number: ERJ-2RKF2200X; Mistral Part No: 110011070017-R; Package: 0402; Part_type: RESISTORS\FIXED; Project: LSM; RoHS: RoHS; Temperature: -55°C+155°C; Tolerance: 1%; Voltage: NA; Wattage: 1/10W; Weight: 0.8mg; Datasheet: Y:\MIS_DATABASE\DATASHEETS\RESISTORS\PAN-ERJSER_NOV17.PDF
SW1 = SW3_SLIDE_EG1218: SWITCH SLIDE SPST 30V TH; Chkd/date: SHREESHAIL/180607; Crtd /date: MAZHAR/160107; Custom_Duty: 24%; Customs_HS_Code: 85369090; Distributor_name: MOUSER; Distributor_part_number: 612-EG1218; Height: 7.40MM; Mfr_name: E-SWITCH; Mistral Part No: 130009030349; Package: THRU-HOLE; Part_type: ELECTRO-MECHANICAL\SWITCH; Project: OMAP2430_OSK; Datasheet: Y:\MIS_DATABASE\DATASHEETS\MISC\SWITCHES\EG.PDF
U13 = SN74LVC2G14DCKR_SC-70: IC DUAL SCHMITT-TRIGGER INVERTER SC70-6; Chkd/date: SHREESHAIL/120106; Crtd /date: MAZHAR/020505; Custom_Duty: 15%; Customs_HS_Code: 85423100; Distributor_name: DIGIKEY; Distributor_part_number: 296-13011-1-ND; Height: 1.10MM; Mfr_name: TEXAS INSTRUMENTS; Mfr_part_number: SN74LVC2G14DCKR; Mistral Part No: 141009030243; Part_type: ICS\DIGITAL\GATES; Project: FPI; Datasheet: Y:\MIS_DATABASE\DATASHEETS\ICS\DIGITAL\GATES\SN74LVC2G14.PDF

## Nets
DGND: C45.2 C46.2 C50.2 C74.2 C77.2 C79.2 C80.2 C82.2 C83.2 C84.2 C86.2 C87.2 C93.2 C94.2 C95.2 C97.2 C100.2 C101.2 C102.2 C109.2 C136.2 C157.2 C161.2 C164.2 C165.2 C166.2 C167.2 C171.2 C178.2 C179.2 C180.2 C181.2 C182.2 C188.2 C190.2 C191.2 C192.2 C193.2 C194.2 C195.2 C298.2 C303.2 C311.2 C312.2 C369.2 C765.2 C766.2 J8.1 J8.3 J10.8 MOD1.2(GND) R99.2 R102.2 R112.2 R116.1 R158.1 R166.1 R174.1 R183.2 R213.2 R263.1 R272.1 R278.1 R498.2 U13.2(GND) U19.2(AGNDAD2) U19.11(DGND2) U19.16(AGNDDA1) U19.33(AGNDDA2) U19.47(DGND1) U19.50(AGNDAD1) U19.65(EP) U21.4(GND) U25.4(GND) U32.2(AGNDAD2) U32.11(DGND2) U32.16(AGNDDA1) U32.33(AGNDDA2) U32.47(DGND1) U32.50(AGNDAD1) U32.65(EP) U179.4(V-) U180.4(V-) ; also on sheet 5 6 7 8 9 10 11 12 13 14 15 16 17 18 19 20 21
V3V3_OPTICAL: C46.1 L1.2 MOD1.1(VCC)
VCC_3V3: C45.1 C50.1 C86.1 C109.1 C136.1 C182.1 L1.1 R152.2 R171.1 R264.1 R267.2 U13.5(VCC) U21.8(VCC) U25.8(VCC) ; also on sheet 5 14 15 16 17 18 19 20 21
VCC_5V0: C77.1 C97.1 C167.1 C195.1 FL8.1 FL9.1 FL11.1 FL12.1 ; also on sheet 5 6 9 14 15 17
VCCAD1_5V0: C164.1 C165.1 C166.1 C178.1 C179.1 FL11.2 TP162.1(TP) U32.3(VCCAD2) U32.49(VCCAD1)
VCCAD2_5V0: C93.1 C94.1 C95.1 C101.1 C102.1 FL9.2 TP165.1(TP) U19.3(VCCAD2) U19.49(VCCAD1)
VCCDA1_5V0: C188.1 C190.1 C191.1 C192.1 C194.1 FL12.2 TP161.1(TP) U32.14(VCCDA1) U32.34(VCCDA2)
VCCDA2_5V0: C79.1 C80.1 C82.1 C83.1 C84.1 FL8.2 TP164.1(TP) U19.14(VCCDA1) U19.34(VCCDA2)
VCCP_IN: C765.1 C766.1 U179.8(V+) U180.8(V+) ; also on sheet 6 7 8 10 11 12
VDD_3V3_CODEC1: C180.1 C181.1 C369.1 R267.1 R271.2 R277.2 TP169.1(TP) U32.12(VDD2) U32.46(VDD1)
VDD_3V3_CODEC2: C87.1 C298.1 C303.1 R152.1 R159.2 R167.2 TP170.1(TP) U19.12(VDD2) U19.46(VDD1)
AIN1_N: TP59.1(TP) U32.51(VIN1-) ; also on sheet 7
AIN1_P: TP58.1(TP) U32.52(VIN1+) ; also on sheet 7
AIN2_N: TP61.1(TP) U32.53(VIN2-) ; also on sheet 7
AIN2_P: TP60.1(TP) U32.54(VIN2+) ; also on sheet 7
AIN3_N: U32.55(VIN3-) ; also on sheet 8
AIN3_P: U32.56(VIN3+) ; also on sheet 8
AIN4_N: U32.57(VIN4-) ; also on sheet 8
AIN4_P: U32.58(VIN4+) ; also on sheet 8
AIN5_N: U32.61(VIN5-) ; also on sheet 6
AIN5_P: U32.62(VIN5+) ; also on sheet 6
AIN6_N: U32.63(VIN6-) ; also on sheet 6
AIN6_P: U32.64(VIN6+) ; also on sheet 6
AOUT1_N: U32.32(VOUT1-) ; also on sheet 9
AOUT1_P: U32.31(VOUT1+) ; also on sheet 9
AOUT2_N: U32.30(VOUT2-) ; also on sheet 9
AOUT2_P: U32.29(VOUT2+) ; also on sheet 9
AOUT3_N: TP63.1(TP) U32.28(VOUT3-) ; also on sheet 9
AOUT3_P: TP62.1(TP) U32.27(VOUT3+) ; also on sheet 9
AOUT4_N: TP65.1(TP) U32.26(VOUT4-) ; also on sheet 9
AOUT4_P: TP64.1(TP) U32.25(VOUT4+) ; also on sheet 9
AOUT5_N: U32.24(VOUT5-) ; also on sheet 9
AOUT5_P: U32.23(VOUT5+) ; also on sheet 9
AOUT6_N: U32.22(VOUT6-) ; also on sheet 9
AOUT6_P: U32.21(VOUT6+) ; also on sheet 9
AOUT7_N: TP66.1(TP) U32.20(VOUT7-) ; also on sheet 9
AOUT7_P: TP67.1(TP) U32.19(VOUT7+) ; also on sheet 9
AOUT8_N: TP69.1(TP) U32.18(VOUT8-) ; also on sheet 9
AOUT8_P: TP68.1(TP) U32.17(VOUT8+) ; also on sheet 9
BIN1_N: TP71.1(TP) U19.51(VIN1-) ; also on sheet 11
BIN1_P: TP70.1(TP) U19.52(VIN1+) ; also on sheet 11
BIN2_N: TP72.1(TP) U19.53(VIN2-) ; also on sheet 11
BIN2_P: TP73.1(TP) U19.54(VIN2+) ; also on sheet 11
BIN3_N: U19.55(VIN3-) ; also on sheet 12
BIN3_P: U19.56(VIN3+) ; also on sheet 12
BIN4_N: U19.57(VIN4-) ; also on sheet 12
BIN4_P: U19.58(VIN4+) ; also on sheet 12
BIN5_N: TP76.1(TP) U19.61(VIN5-) ; also on sheet 10
BIN5_P: TP75.1(TP) U19.62(VIN5+) ; also on sheet 10
BIN6_N: TP74.1(TP) U19.63(VIN6-) ; also on sheet 10
BIN6_P: TP77.1(TP) U19.64(VIN6+) ; also on sheet 10
BOUT1_N: U19.32(VOUT1-) ; also on sheet 13
BOUT1_P: U19.31(VOUT1+) ; also on sheet 13
BOUT2_N: U19.30(VOUT2-) ; also on sheet 13
BOUT2_P: U19.29(VOUT2+) ; also on sheet 13
BOUT3_N: TP79.1(TP) U19.28(VOUT3-) ; also on sheet 13
BOUT3_P: TP78.1(TP) U19.27(VOUT3+) ; also on sheet 13
BOUT4_N: TP81.1(TP) U19.26(VOUT4-) ; also on sheet 13
BOUT4_P: TP80.1(TP) U19.25(VOUT4+) ; also on sheet 13
BOUT5_N: U19.24(VOUT5-) ; also on sheet 13
BOUT5_P: U19.23(VOUT5+) ; also on sheet 13
BOUT6_N: U19.22(VOUT6-) ; also on sheet 13
BOUT6_P: U19.21(VOUT6+) ; also on sheet 13
BOUT7_N: TP82.1(TP) U19.20(VOUT7-) ; also on sheet 13
BOUT7_P: TP83.1(TP) U19.19(VOUT7+) ; also on sheet 13
BOUT8_N: TP85.1(TP) U19.18(VOUT8-) ; also on sheet 13
BOUT8_P: TP84.1(TP) U19.17(VOUT8+) ; also on sheet 13
CODEC1_ACLKX: R188.2 U32.7(BCKAD) U32.36(BCKDA)
CODEC1_I2C_ADD0: R271.1 R272.2 U32.45(MS/ADR0/MD0)
CODEC1_I2C_ADD1: R277.1 R278.2 U32.44(MDO/ADR1/MD1)
CODEC1_MODE: R263.2 R264.2 U32.48(MODE)
CODEC1_OVF: TP13.1(TP) U32.5(OVF)
CODEC1_SCKI: R215.2 U32.41(SCKI)
CODEC1_VREFAD1: C157.1 U32.59(VREFAD1)
CODEC1_VREFAD2: C161.1 U32.60(VREFAD2)
CODEC1_ZERO: TP14.1(TP) U32.13(ZERO)
CODEC2_ACLKX: R187.2 U19.7(BCKAD) U19.36(BCKDA)
CODEC2_I2C_ADD0: R166.2 R167.1 U19.45(MS/ADR0/MD0)
CODEC2_I2C_ADD1: R158.2 R159.1 U19.44(MDO/ADR1/MD1)
CODEC2_MODE: R171.2 R174.2 U19.48(MODE)
CODEC2_OVF: TP3.1(TP) U19.5(OVF)
CODEC2_SCKI: R214.2 U19.41(SCKI)
CODEC2_VREFAD1: C312.1 U19.59(VREFAD1)
CODEC2_VREFAD2: C311.1 U19.60(VREFAD2)
CODEC2_ZERO: TP2.1(TP) U19.13(ZERO)
CODEC_RESETn: R498.1 U19.4(RST#) U32.4(RST#) ; also on sheet 5
CODEC_SCKI: R538.1 ; also on sheet 5
DIR_JACK: C47.2 J8.2 R102.1
DIR_JACK_ac: C47.1 R100.2 U13.1(A)
DIR_RXIN: SW1.2(COM) ; also on sheet 19
DIR_RXIN_COAX: SW1.1 U13.4(Y)
DIT_GND: J9.1 J9.3 R116.2
DIT_JACK: J9.2 R104.2
DIT_JACK_ac: C51.1 R112.1 R119.2
I2C3_SCL: U19.42(MC/SCL/FMT) U32.42(MC/SCL/FMT) ; also on sheet 5 18 20
I2C3_SDA: U19.43(MDI/SDA/DEMP) U32.43(MDI/SDA/DEMP) ; also on sheet 5 18 20
McASP0_ACLKX: TP94.1(TP) U21.2(1A) U21.5(2A) ; also on sheet 5
McASP0_AFSX: TP93.1(TP) U19.6(LRCKAD) U19.35(LRCKDA) U32.6(LRCKAD) U32.35(LRCKDA) ; also on sheet 5
McASP0_AXR0: TP87.1(TP) U32.37(DIN1) ; also on sheet 5
McASP0_AXR1: TP86.1(TP) U32.38(DIN2) ; also on sheet 5
McASP0_AXR2: TP88.1(TP) U32.39(DIN3) ; also on sheet 5
McASP0_AXR3: TP89.1(TP) U32.40(DIN4) ; also on sheet 5
McASP0_AXR4: R270.2 TP90.1(TP) ; also on sheet 5
McASP0_AXR4_R: R270.1 U32.8(DOUT1)
McASP0_AXR5: R274.2 TP91.1(TP) ; also on sheet 5
McASP0_AXR5_R: R274.1 U32.9(DOUT2)
McASP0_AXR6: R276.2 TP92.1(TP) ; also on sheet 5
McASP0_AXR6_R: R276.1 U32.10(DOUT3)
McASP0_AXR7: TP95.1(TP) U19.37(DIN1) ; also on sheet 5
McASP0_AXR8: TP96.1(TP) U19.38(DIN2) ; also on sheet 5
McASP0_AXR9: TP97.1(TP) U19.39(DIN3) ; also on sheet 5
McASP0_AXR10: TP98.1(TP) U19.40(DIN4) ; also on sheet 5
McASP0_AXR11: R161.2 TP99.1(TP) ; also on sheet 5
McASP0_AXR11_R: R161.1 U19.8(DOUT1)
McASP0_AXR12: R157.2 TP100.1(TP) ; also on sheet 5
McASP0_AXR12_R: R157.1 U19.9(DOUT2)
McASP0_AXR13: R154.2 TP101.1(TP) ; also on sheet 5
McASP0_AXR13_R: R154.1 U19.10(DOUT3)
McASP2_AXR0: R119.1 ; also on sheet 5
McASP10_ACLKX/EHRPWM0_SYNCI: J10.2 ; also on sheet 5
McASP10_AFSX/EHRPWM0_SYNCO: J10.3 ; also on sheet 5
MCASP10_AXR0/EHRPWM_TZn_IN0: J10.4 ; also on sheet 5
McASP10_AXR1/EHRPWM0_A: J10.5 ; also on sheet 5
McASP10_AXR2/EHRPWM1_B: J10.6 ; also on sheet 5
McASP10_AXR3/EHRPWM_TZn_IN1: J10.1 ; also on sheet 5
R_CODEC1_ACLKX: R188.1 U21.6(1Y)
R_CODEC1_SCKI: R215.1 U25.6(1Y)
R_CODEC2_ACLKX: R187.1 U21.3(2Y)
R_CODEC2_SCKI: R214.1 U25.3(2Y)
REFCLK0: R539.1 ; also on sheet 5
REFCLK0/REFCLK2: R538.2 R539.2 TP9.1(TP) U25.2(1A) U25.5(2A)
RXIN_OPTICAL: MOD1.3(VOUT) SW1.3
VCOMAD1: U179.1(OUTA) U179.2(-INA) ; also on sheet 6 7 8
VCOMAD1_CODEC: C171.1 U32.1(VCOMAD) U179.3(+INA) U179.5(+INB)
VCOMAD1_SPARE: TP171.1(TP) U179.6(-INB) U179.7(OUTB)
VCOMAD2: U180.1(OUTA) U180.2(-INA) ; also on sheet 10 11 12
VCOMAD2_CODEC: C100.1 U19.1(VCOMAD) U180.3(+INA) U180.5(+INB)
VCOMAD2_SPARE: TP172.1(TP) U180.6(-INB) U180.7(OUTB)
VCOMDA1: C193.1 U32.15(VCOMDA)
VCOMDA2: C74.1 U19.15(VCOMDA)
N24793440: R213.1 U25.1(\\~{1}\\~{O}\E) U25.7(\\~{2}\\~{O}\\E)
N24817584: R183.1 U21.1(\\~{1}\\~{O}\E) U21.7(\\~{2}\\~{O}\\E)
N24985508: R99.1 R100.1 U13.3(A) U13.6(Y)
N24986462: C51.2 R104.1

Not connected (* = marked no-connect by the designer): J10 7*; MOD1 4(NC1)* 5(NC2)*

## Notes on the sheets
sheet 22
- AUDIO I/F CODEC-B
- Resistor Isolation option provided for Debug purpose
- 2x STEREO MIC-IN
- 4x STEREO LINE-OUT
- 1x STEREO LINE-IN
- From  Expansion
  Connector
- To Expansion
  connector
- Note: MODE tied to DGND with 0E Resistor for
  Software Control (default)
- PCB Note: Short at single point or segment
  signals/plane to isolate analog from digital
  signals
- Codec2
- I2C Address SEL
- Note: Use for input signal
  conditioning.
- 7b' I2C Address 0x46 (default)
sheet 23
- AUDIO I/F CODEC - A
- Resistor Isolation option provided for Debug purpose
- 2x STEREO MIC-IN
- 4x STEREO LINE-OUT
- 1x STEREO LINE-IN
- From  Expansion
  Connector
- To Expansion
  connector
- Codec1
- I2C Address SEL
- Note: MODE tied to DGND with 0E Resistor for
  Software Control (default)
- PCB Note: Short CODEC_AGND and DGND at single point
- 1-to-2 Clock Fanout Buffer
- Note: Use for input signal
  conditioning.
- 7b' I2C Address 0x47 (default)
- 1-to-2 Clock Fanout Buffer
sheet 24
- GPIO EXPANDER MAP/TABLE
sheet 25
- Digital Audio Interface Receiver (DIR) INPUT
- DIR: FIBER OPTIC RECEIVER MODULE
- Tantalum capacitor
- DIR INPUT SELECTION SWITCH
- DIR: COAXIAL RCA
  CONNECTOR & LINE DRIVER
- RCA Jack (Black)
- Silkscreen:
  "DIR"
- Digital Audio Interface Transmit (DIT)
- RCA Jack (Red)
- Silkscreen:
  "DIT"
